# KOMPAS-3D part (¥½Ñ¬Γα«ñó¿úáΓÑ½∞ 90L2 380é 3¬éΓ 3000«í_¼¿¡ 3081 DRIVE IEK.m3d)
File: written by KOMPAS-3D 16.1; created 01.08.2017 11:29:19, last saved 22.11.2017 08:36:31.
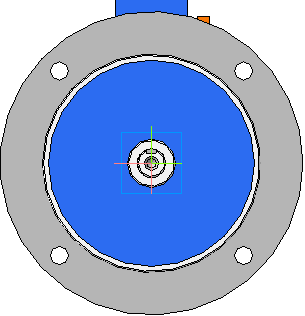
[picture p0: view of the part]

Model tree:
1. Операция без истории:1
2. Эскиз:2
3. Вырезать элемент выдавливания:2
     Расстояние 2 = 60; Расстояние 1 = 10
4. Эскиз:3
5. Вырезать элемент выдавливания:3
     Расстояние 2 = 60; Расстояние 1 = 160
6. Эскиз:4
7. Вырезать элемент выдавливания:4
     Расстояние 2 = 4; Расстояние 1 = 40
